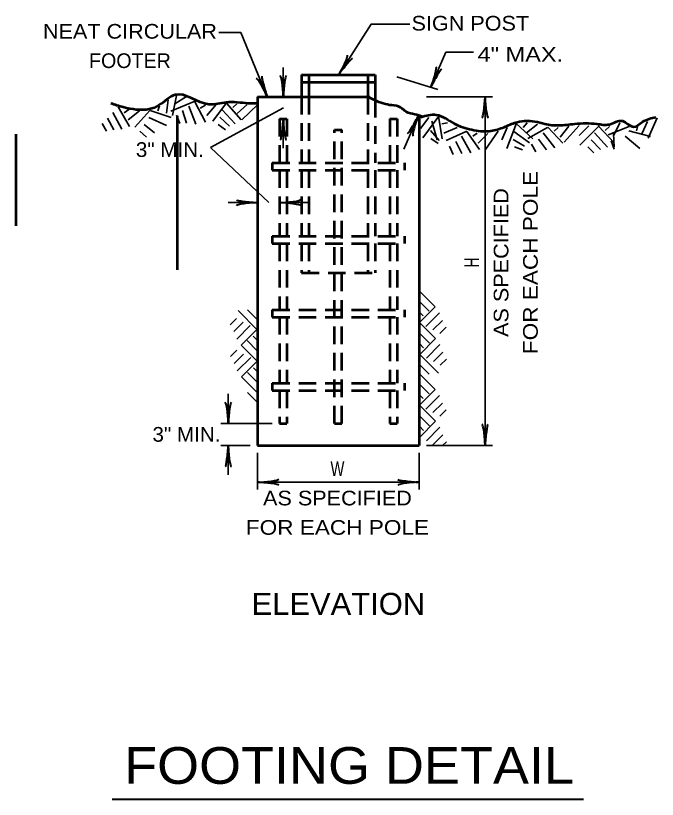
# Model space of a CAD drawing. Extents: x -2 to 678, y -1 to 439.
# Drawn here: x 365 to 452.4, y 138.6 to 245.3 of the extents above; entities that cross this region are included whole.
import ezdxf
from ezdxf.enums import TextEntityAlignment as Align

# ---------------------------------------------------------------- set-up
doc = ezdxf.new("R2010")
doc.units = 0
doc.header["$LTSCALE"] = 0.8
doc.linetypes.add('MEDIUM_DASHED', pattern=[4.5, 3, -1.5])
doc.layers.add('1', color=7, linetype='Continuous', lineweight=35)

msp = doc.modelspace()

# ---------------------------------------------------------------- linework, layer by layer
at = {"layer": '1'}
for p, q in [((421.5607, 235.5305), (423.6368, 240.319)), ((423.6368, 240.319), (427.4058, 240.319)), ((401.4802, 234.2558), (401.4802, 238.2558)), ((416.9355, 236.9603), (422.5276, 235.2315)), ((385.8028, 233.8592), (385.5772, 232.0061)), ((386.9775, 234.6502), (386.3639, 231.6867)), ((388.2863, 234.2928), (386.7009, 233.3072)), ((420.9802, 234.2558), (429.9802, 234.2558)), ((428.9802, 234.2558), (428.9802, 186.7558)), ((378.9817, 232.8935), (380.5315, 230.1958)), ((384.6288, 233.0141), (384.3913, 232.3181)), ((389.5738, 233.6958), (386.1398, 232.3042)), ((388.6144, 232.9758), (389.5617, 230.5369)), ((389.4094, 233.5457), (390.8876, 230.8081)), ((390.8658, 233.1107), (390.1633, 232.7152)), ((392.3204, 233.19), (391.0803, 231.683)), ((401.5089, 232.766), (391.5729, 227.352)), ((393.7235, 233.4253), (391.8698, 230.9441)), ((393.7214, 233.3678), (395.7473, 231.1194)), ((395.1396, 233.2943), (394.5938, 232.8014)), ((396.5777, 233.2209), (395.1923, 231.9698)), ((397.9997, 233.2155), (395.8338, 231.1017)), ((378.2505, 232.1308), (379.5037, 229.8342)), ((380.4554, 232.514), (379.7873, 232.0627)), ((381.8848, 232.3172), (380.3541, 231.1066)), ((383.3128, 232.401), (381.2423, 230.0977)), ((383.3543, 232.3879), (386.2187, 231.4108)), ((386.9533, 231.7355), (387.3754, 230.6099)), ((387.7374, 232.3903), (388.2935, 230.6677)), ((393.1655, 232.4834), (394.9292, 230.5702)), ((417.9185, 227.1302), (419.9075, 231.7177)), ((376.7911, 230.6056), (377.3736, 229.554)), ((377.5342, 231.3432), (378.3927, 229.7497)), ((383.1709, 231.4097), (385.5534, 230.3632)), ((392.8243, 231.4714), (394.1572, 230.2467)), ((401.4802, 227.2558), (401.4802, 231.2558)), ((421.2917, 231.4096), (420.1795, 229.9104)), ((422.6964, 231.6178), (420.4887, 228.6421)), ((421.7024, 230.9237), (422.4299, 228.4106)), ((422.6246, 231.5914), (423.1304, 228.5215)), ((423.8598, 230.7056), (423.0668, 230.5606)), ((433.2671, 230.6739), (431.9293, 227.2186)), ((433.1912, 230.6087), (435.4973, 228.5203)), ((434.7093, 230.6838), (434.1787, 230.0768)), ((447.3197, 230.6881), (446.4954, 228.9191)), ((451.1196, 230.889), (450.3493, 229.1885)), ((452.4485, 231.3893), (451.1997, 228.6325)), ((381.9496, 229.5514), (382.8503, 228.7343)), ((382.5358, 230.4894), (383.945, 229.3533)), ((392.6237, 230.464), (393.5947, 229.7317)), ((421.5302, 229.6611), (422.7239, 228.3003)), ((425.1653, 230.0867), (423.3791, 229.3007)), ((426.4951, 229.5873), (423.68, 228.296)), ((426.4953, 229.5358), (428.2378, 227.0613)), ((430.7422, 229.5611), (429.0321, 227.0642)), ((431.9736, 230.0836), (431.2378, 228.3679)), ((432.8844, 229.5054), (435.0168, 227.9893)), ((436.1355, 230.5344), (434.6016, 229.3278)), ((437.4857, 230.0889), (434.7963, 228.5528)), ((437.5122, 230.1173), (439.5899, 227.9168)), ((438.9327, 230.0841), (438.4112, 229.5656)), ((440.3695, 230.236), (439.208, 228.7745)), ((441.7834, 230.3347), (439.7738, 228.0717)), ((443.1027, 230.2892), (441.7831, 228.9688)), ((444.5223, 230.2772), (441.8838, 227.6759)), ((444.4207, 230.2571), (446.5465, 227.9853)), ((445.9398, 230.2067), (445.3609, 229.6456)), ((448.6232, 230.2116), (445.7479, 229.0603)), ((448.5723, 229.6239), (451.5016, 228.8632)), ((449.7954, 230.3461), (449.6173, 229.6326)), ((421.5892, 228.5827), (422.5631, 227.8777)), ((425.7594, 228.8931), (427.0184, 226.6157)), ((427.8943, 229.2929), (427.2931, 228.8696)), ((429.3409, 229.2647), (428.0405, 227.9255)), ((432.7828, 228.4321), (434.3446, 227.5168)), ((436.2612, 228.4955), (437.3323, 227.0362)), ((436.8913, 229.3498), (438.5033, 227.3072)), ((443.8965, 229.3328), (445.6689, 227.4082)), ((446.4893, 229.2463), (446.5868, 227.4387)), ((448.0462, 228.8869), (450.0502, 227.227)), ((424.1122, 227.5137), (424.6142, 226.4059)), ((424.9859, 228.1626), (425.7926, 226.5421)), ((432.9714, 227.4429), (434.0922, 227.008)), ((435.2962, 227.8119), (435.8947, 226.7531)), ((442.9622, 227.4483), (443.8162, 226.6022)), ((443.4342, 228.3738), (444.6822, 227.0625)), ((446.1412, 228.2577), (446.5881, 227.1266)), ((399.4894, 219.837), (391.5729, 227.352)), ((393.9802, 219.837), (397.9802, 219.837)), ((400.9802, 219.837), (404.9802, 219.837)), ((420.0202, 207.7757), (422.1602, 205.6358)), ((420.0202, 206.3558), (421.3402, 205.0358)), ((397.9402, 202.5157), (395.3202, 205.1358)), ((397.9402, 203.9357), (396.6202, 205.2558)), ((420.0202, 203.4957), (422.1602, 205.6358)), ((395.1002, 204.0557), (394.2602, 203.1958)), ((420.0202, 204.9158), (420.5402, 204.3957)), ((420.9202, 202.9758), (422.7602, 204.8157)), ((396.0202, 203.5557), (394.7402, 202.2757)), ((396.9802, 203.0957), (395.1402, 201.2357)), ((420.0202, 203.4957), (422.2202, 201.3157)), ((421.8802, 202.5157), (423.1602, 203.7957)), ((422.8002, 201.9957), (423.6602, 202.8558)), ((397.9402, 202.6157), (395.7402, 200.4158)), ((420.0202, 202.0757), (421.4002, 200.6958)), ((397.9402, 199.6557), (396.5602, 201.0358)), ((397.9402, 201.0957), (397.3602, 201.6557)), ((420.0202, 199.1157), (422.2202, 201.3157)), ((395.1602, 199.7357), (394.3002, 198.8757)), ((397.9402, 198.2357), (395.7402, 200.4158)), ((420.0202, 200.6358), (420.6002, 200.0757)), ((420.9802, 198.6358), (422.8202, 200.4957)), ((396.0802, 199.2157), (394.8002, 197.9357)), ((397.0402, 198.7558), (395.2002, 196.9158)), ((420.0202, 199.2157), (422.6402, 196.5957)), ((421.9402, 198.1757), (423.2202, 199.4557)), ((397.9402, 198.2357), (395.8002, 196.0957)), ((420.0202, 197.7957), (421.3402, 196.4758)), ((422.8602, 197.6757), (423.7002, 198.5358)), ((397.9402, 195.3757), (396.6202, 196.6958)), ((397.9402, 196.8157), (397.4202, 197.3357)), ((420.0202, 196.5157), (422.1602, 194.3757)), ((397.9402, 193.9557), (395.8002, 196.0957)), ((420.0202, 195.0957), (421.3402, 193.7757)), ((420.0202, 192.2357), (422.1602, 194.3757)), ((393.9855, 189.7699), (393.9855, 193.7699)), ((397.9402, 192.6358), (396.6202, 193.9557)), ((420.0202, 193.6557), (420.5402, 193.1358)), ((420.9202, 191.7157), (422.7602, 193.5557)), ((420.0202, 192.2357), (422.2202, 190.0557)), ((421.8802, 191.2558), (423.1602, 192.5358)), ((422.8002, 190.7357), (423.6602, 191.5957)), ((420.0202, 190.8157), (421.4002, 189.4357)), ((420.0202, 187.8558), (422.2202, 190.0557)), ((399.9802, 189.7575), (392.9855, 189.7699)), ((420.0202, 189.3757), (420.6002, 188.8157)), ((420.9802, 187.3757), (422.8202, 189.2357)), ((421.7802, 186.7558), (423.2202, 188.1958)), ((423.1923, 186.7558), (423.7002, 187.2757)), ((396.9802, 186.7558), (392.9802, 186.7558)), ((393.9802, 186.7558), (393.9802, 182.7558)), ((397.9802, 185.7558), (397.9802, 180.7558)), ((419.9802, 185.7558), (419.9802, 180.7558)), ((420.9802, 186.7558), (429.9802, 186.7558)), ((397.9802, 181.7558), (419.9802, 181.7558))]:
    msp.add_line(p, q, dxfattribs=at)
at = {"layer": '1', "lineweight": 53}
for p, q in [((403.9802, 237.2558), (413.9802, 237.2558)), ((403.9802, 237.2558), (403.9802, 234.2558)), ((404.9802, 237.2558), (404.9802, 234.2558)), ((412.9802, 237.2558), (412.9802, 234.2558)), ((413.9802, 237.2558), (413.9802, 233.8352)), ((403.9802, 236.2558), (413.9802, 236.2558)), ((397.9802, 234.2558), (413.2576, 234.2558)), ((397.9802, 234.2558), (397.9802, 186.7558)), ((387.0159, 231.6681), (387.0159, 210.6681)), ((419.9802, 231.6968), (419.9802, 186.7558)), ((365.0159, 229.1681), (365.0159, 216.6681)), ((397.9802, 186.7558), (419.9802, 186.7558))]:
    msp.add_line(p, q, dxfattribs=at)
at = {"layer": '1', "linetype": 'MEDIUM_DASHED', "lineweight": 53}
for p, q in [((403.9802, 234.2558), (403.9802, 225.2558)), ((404.9802, 234.2558), (404.9802, 225.2558)), ((412.9802, 234.2558), (412.9802, 225.2558)), ((413.9802, 233.8352), (413.9802, 225.2558)), ((400.9802, 231.2558), (401.9802, 231.2558)), ((400.9802, 231.2558), (400.9802, 225.2558)), ((401.9802, 231.2558), (401.9802, 225.2558)), ((415.9802, 231.2558), (416.9802, 231.2558)), ((415.9802, 231.2558), (415.9802, 225.2558)), ((416.9802, 231.2558), (416.9802, 225.2558)), ((408.4802, 189.7558), (408.4802, 229.7558)), ((408.4802, 229.7558), (409.4802, 229.7558)), ((409.4802, 189.7558), (409.4802, 229.7558)), ((399.9802, 225.2558), (417.9802, 225.2558)), ((399.9802, 225.2558), (399.9802, 224.2558)), ((417.9802, 225.2558), (417.9802, 224.2558)), ((399.9802, 224.2558), (417.9802, 224.2558)), ((400.9802, 224.2558), (400.9802, 215.2558)), ((401.9802, 224.2558), (401.9802, 215.2558)), ((403.9802, 224.2558), (403.9802, 215.2558)), ((404.9802, 224.2558), (404.9802, 215.2558)), ((412.9802, 224.2558), (412.9802, 215.2558)), ((413.9802, 224.2558), (413.9802, 215.2558)), ((415.9802, 224.2558), (415.9802, 215.2558)), ((416.9802, 224.2558), (416.9802, 215.2558)), ((399.9802, 215.2558), (417.9802, 215.2558)), ((399.9802, 215.2558), (399.9802, 214.2558)), ((417.9802, 215.2558), (417.9802, 214.2558)), ((399.9802, 214.2558), (417.9802, 214.2558)), ((400.9802, 214.2558), (400.9802, 205.2558)), ((401.9802, 214.2558), (401.9802, 205.2558)), ((403.9802, 214.2558), (403.9802, 210.2558)), ((404.9802, 214.2558), (404.9802, 210.2558)), ((412.9802, 214.2558), (412.9802, 210.2558)), ((413.9802, 214.2558), (413.9802, 210.2558)), ((415.9802, 214.2558), (415.9802, 205.2558)), ((416.9802, 214.2558), (416.9802, 205.2558)), ((403.9802, 210.2558), (413.9802, 210.2558)), ((399.9802, 205.2558), (417.9802, 205.2558)), ((399.9802, 205.2558), (399.9802, 204.2558)), ((417.9802, 205.2558), (417.9802, 204.2558)), ((399.9802, 204.2558), (417.9802, 204.2558)), ((400.9802, 204.2558), (400.9802, 195.2558)), ((401.9802, 204.2558), (401.9802, 195.2558)), ((415.9802, 204.2558), (415.9802, 195.2558)), ((416.9802, 204.2558), (416.9802, 195.2558)), ((399.9802, 195.2558), (417.9802, 195.2558)), ((399.9802, 195.2558), (399.9802, 194.2558)), ((417.9802, 195.2558), (417.9802, 194.2558)), ((399.9802, 194.2558), (417.9802, 194.2558)), ((400.9802, 194.2558), (400.9802, 189.7558)), ((401.9802, 194.2558), (401.9802, 189.7558)), ((415.9802, 194.2558), (415.9802, 189.7558)), ((416.9802, 194.2558), (416.9802, 189.7558)), ((400.9802, 189.7558), (401.9802, 189.7558)), ((408.4802, 189.7558), (409.4802, 189.7558)), ((415.9802, 189.7558), (416.9802, 189.7558))]:
    msp.add_line(p, q, dxfattribs=at)
at = {"layer": '1', "lineweight": 40}
msp.add_line((378.1533, 138.5607), (442.3795, 138.5607), dxfattribs=at)
at = {"layer": '1'}
for points in [[(409.0276, 237.2558), (413.4643, 244.1598), (418.7151, 244.1598)], [(399.299, 234.2558), (395.6927, 243.0284), (392.6995, 243.0284)]]:
    msp.add_lwpolyline(points, dxfattribs=at)
at = {"layer": '1', "lineweight": 40}
for centre, major_axis, ratio, start_param, end_param in [((409.3851, 238.3231), (-0.834, -1.5867), 0.122415, 0.89635335, 3.14159265), ((409.3851, 238.3231), (-0.834, -1.5867), 0.122415, 0.89635335, 3.14159265), ((409.8114, 238.084), (1.0973, 1.3827), 0.07063, 6.28230741, 8.55970261), ((409.8114, 238.084), (1.0973, 1.3827), 0.07063, 6.28230741, 8.55970261), ((421.7412, 236.6416), (-0.5671, -1.7005), 0.122415, 0.89635335, 3.14159265), ((421.7412, 236.6416), (-0.5671, -1.7005), 0.122415, 0.89635335, 3.14159265), ((422.2005, 236.4744), (-0.8599, -1.5416), 0.07063, 3.14071475, 5.41810995), ((422.2005, 236.4744), (-0.8599, -1.5416), 0.07063, 3.14071475, 5.41810995), ((399.0687, 235.3726), (-0.5054, 1.6913), 0.07063, 6.28230741, 8.55970261), ((399.0687, 235.3726), (-0.5054, 1.6913), 0.07063, 6.28230741, 8.55970261), ((401.2039, 235.3469), (0.1562, -1.7857), 0.122415, 0.89635335, 3.14159265), ((401.2039, 235.3469), (0.1562, -1.7857), 0.122415, 0.89635335, 3.14159265), ((401.6918, 235.3763), (-0.1757, -1.7565), 0.07063, 3.14071475, 5.41810995), ((401.6918, 235.3763), (-0.1757, -1.7565), 0.07063, 3.14071475, 5.41810995), ((398.6286, 235.16), (0.8234, -1.5922), 0.122415, 0.89635335, 3.14159265), ((398.6286, 235.16), (0.8234, -1.5922), 0.122415, 0.89635335, 3.14159265), ((428.7686, 233.1352), (0.1757, 1.7565), 0.07063, 3.14071475, 5.41810995), ((428.7686, 233.1352), (0.1757, 1.7565), 0.07063, 3.14071475, 5.41810995), ((429.2565, 233.1646), (-0.1562, 1.7857), 0.122415, 0.89635335, 3.14159265), ((429.2565, 233.1646), (-0.1562, 1.7857), 0.122415, 0.89635335, 3.14159265), ((419.2676, 230.7738), (0.8599, 1.5416), 0.07063, 3.14071475, 5.41810995), ((419.7269, 230.6066), (0.5671, 1.7004), 0.122415, 0.89635335, 3.14159265), ((401.2686, 230.1352), (0.1757, 1.7565), 0.07063, 3.14071475, 5.41810995), ((401.2686, 230.1352), (0.1757, 1.7565), 0.07063, 3.14071475, 5.41810995), ((401.7565, 230.1646), (-0.1562, 1.7857), 0.122415, 0.89635335, 3.14159265), ((401.7565, 230.1646), (-0.1562, 1.7857), 0.122415, 0.89635335, 3.14159265), ((396.8597, 220.0486), (1.7565, -0.1757), 0.07063, 3.14071475, 5.41810995), ((396.8597, 220.0486), (1.7565, -0.1757), 0.07063, 3.14071475, 5.41810995), ((402.0714, 220.1133), (-1.7857, -0.1562), 0.122415, 0.89635335, 3.14159265), ((396.889, 219.5607), (1.7857, 0.1562), 0.122415, 0.89635335, 3.14159265), ((396.889, 219.5607), (1.7857, 0.1562), 0.122415, 0.89635335, 3.14159265), ((402.1007, 219.6254), (-1.7565, 0.1757), 0.07063, 3.14071475, 5.41810995), ((393.7092, 190.8611), (0.1562, -1.7857), 0.122415, 0.89635335, 3.14159265), ((393.7092, 190.8611), (0.1562, -1.7857), 0.122415, 0.89635335, 3.14159265), ((394.1971, 190.8904), (-0.1757, -1.7565), 0.07063, 3.14071475, 5.41810995), ((394.1971, 190.8904), (-0.1757, -1.7565), 0.07063, 3.14071475, 5.41810995), ((428.7039, 187.8469), (0.1562, -1.7857), 0.122415, 0.89635335, 3.14159265), ((428.7039, 187.8469), (0.1562, -1.7857), 0.122415, 0.89635335, 3.14159265), ((429.1918, 187.8763), (-0.1757, -1.7565), 0.07063, 3.14071475, 5.41810995), ((429.1918, 187.8763), (-0.1757, -1.7565), 0.07063, 3.14071475, 5.41810995), ((393.7686, 185.6352), (0.1757, 1.7565), 0.07063, 3.14071475, 5.41810995), ((393.7686, 185.6352), (0.1757, 1.7565), 0.07063, 3.14071475, 5.41810995), ((394.2565, 185.6646), (-0.1562, 1.7857), 0.122415, 0.89635335, 3.14159265), ((394.2565, 185.6646), (-0.1562, 1.7857), 0.122415, 0.89635335, 3.14159265), ((399.1007, 181.5441), (-1.7565, 0.1757), 0.07063, 3.14071475, 5.41810995), ((399.1007, 181.5441), (-1.7565, 0.1757), 0.07063, 3.14071475, 5.41810995), ((399.0714, 182.032), (-1.7857, -0.1562), 0.122415, 0.89635335, 3.14159265), ((399.0714, 182.032), (-1.7857, -0.1562), 0.122415, 0.89635335, 3.14159265), ((418.889, 181.4795), (1.7857, 0.1562), 0.122415, 0.89635335, 3.14159265), ((418.889, 181.4795), (1.7857, 0.1562), 0.122415, 0.89635335, 3.14159265), ((418.8597, 181.9674), (1.7565, -0.1757), 0.07063, 3.14071475, 5.41810995), ((418.8597, 181.9674), (1.7565, -0.1757), 0.07063, 3.14071475, 5.41810995)]:
    msp.add_ellipse(centre, major_axis=major_axis, ratio=ratio, start_param=start_param, end_param=end_param, dxfattribs=at)
at = {"layer": '1', "lineweight": 53}
for points in [[(397.9802, 233.3366), (396.7173, 233.352), (393.7027, 233.4832), (391.3434, 233.2209), (386.7559, 234.5321), (384.5277, 233.0898), (383.217, 232.5653), (379.6781, 232.8276), (377.9802, 233.3366)], [(420.5193, 231.5422), (419.4042, 231.8621), (418.2308, 232.1974), (417.4486, 232.8123), (416.2752, 233.0917), (415.1018, 233.3152), (412.811, 234.3772)], [(420.2224, 231.4982), (422.3218, 231.8092), (424.7466, 230.6291), (427.1714, 229.7768), (429.5307, 229.5802), (431.3657, 230.0391), (433.0041, 230.6947), (435.7565, 230.8913), (437.1327, 230.5636), (439.0333, 230.3669), (441.196, 230.5636), (444.2106, 230.5636), (445.9145, 230.498), (447.684, 230.9569), (449.1912, 230.1702), (450.4365, 230.8257), (452.2224, 231.4982)]]:
    msp.add_spline(points, degree=3, dxfattribs=at)

# ---------------------------------------------------------------- texts
at = {"layer": '1'}
for s, height, width, p in [('SIGN POST', 2, 1.1, (418.9574, 243.2708)), ('4" MAX.', 2, 1.2, (427.9532, 239.0229)), ('3" MIN.', 2, 1.05, (381.3947, 226.0591)), ('3" MIN.', 2, 1.05, (383.6565, 187.2721)), ('ELEVATION', 3, 1.05, (397.1642, 163.6819)), ('FOOTING DETAIL', 5, 1.1, (379.7962, 140.6737))]:
    msp.add_text(s, height=height, dxfattribs=dict(at, width=width)).set_placement(p)
for s, width, p in [('NEAT CIRCULAR', 1.1, (380.5869, 242.1699)), ('W', 0.75, (408.8598, 182.5955)), ('AS SPECIFIED', 1.1, (408.8598, 178.5955)), ('FOR EACH POLE', 1.15, (408.8599, 174.5955))]:
    msp.add_text(s, height=2, dxfattribs=dict(at, width=width)).set_placement(p, align=Align.CENTER)
msp.add_text('FOOTER', height=2, dxfattribs=at).set_placement((380.5869, 238.1699), align=Align.CENTER)
for s, width, p in [('FOR EACH POLE', 1.15, (436.1552, 211.6756)), ('AS SPECIFIED', 1.1, (432.1552, 211.6755)), ('H', 0.7, (428.1552, 211.6756))]:
    msp.add_text(s, height=2, rotation=90, dxfattribs=dict(at, width=width)).set_placement(p, align=Align.CENTER)

doc.saveas('drawing.dxf')
